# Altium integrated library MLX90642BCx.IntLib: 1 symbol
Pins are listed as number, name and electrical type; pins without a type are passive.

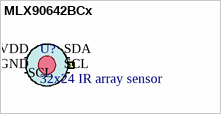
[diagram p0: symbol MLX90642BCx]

## MLX90642BCx
designator U?, comment 32x24 IR array sensor
footprint MLX90642BCA (32x24 IR array sensor in TO39)
footprint MLX90642BCB (32x24 IR array sensor in TO39)
pins: GND (power), SCL, SDA, VDD (power)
